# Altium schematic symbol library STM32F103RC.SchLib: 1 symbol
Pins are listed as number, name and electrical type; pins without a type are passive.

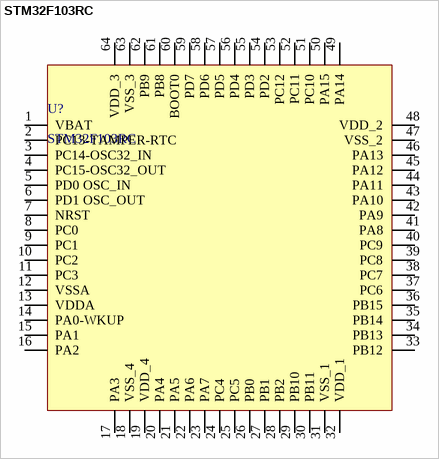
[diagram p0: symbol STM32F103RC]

## STM32F103RC
designator U?
footprint LQFP64_M (64-Pin Thin Quad Flat Pack 0.8 mm Pitch, IPC Low Density)
pins: 1 VBAT, 2 PC13-TAMPER-RTC, 3 PC14-OSC32_IN, 4 PC15-OSC32_OUT, 5 PD0 OSC_IN, 6 PD1 OSC_OUT, 7 NRST, 8 PC0, 9 PC1, 10 PC2, 11 PC3, 12 VSSA, 13 VDDA, 14 PA0-WKUP, 15 PA1, 16 PA2, 17 PA3, 18 VSS_4, 19 VDD_4, 20 PA4, 21 PA5, 22 PA6, 23 PA7, 24 PC4, 25 PC5, 26 PB0, 27 PB1, 28 PB2, 29 PB10, 30 PB11, 31 VSS_1, 32 VDD_1, 33 PB12, 34 PB13, 35 PB14, 36 PB15, 37 PC6, 38 PC7, 39 PC8, 40 PC9, 41 PA8, 42 PA9, 43 PA10, 44 PA11, 45 PA12, 46 PA13, 47 VSS_2, 48 VDD_2, 49 PA14, 50 PA15, 51 PC10, 52 PC11, 53 PC12, 54 PD2, 55 PD3, 56 PD4, 57 PD5, 58 PD6, 59 PD7, 60 BOOT0, 61 PB8, 62 PB9, 63 VSS_3, 64 VDD_3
